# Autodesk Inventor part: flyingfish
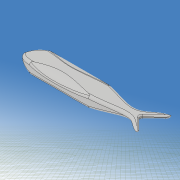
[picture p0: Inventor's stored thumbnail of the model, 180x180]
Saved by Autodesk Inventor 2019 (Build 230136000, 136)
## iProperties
Created: 2020-12
Part Number: flyingfish
Material: 一般
Document SubType Name: Modeling
Designer: kikut
Density: 1 g/cm^3
Appearance: 既定
Mass: 87.6477 g
Surface Area: 156.124 cm^2
Volume: 87.6477 cm^3
Author: kikut
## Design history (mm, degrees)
sketch "スケッチ1"
  geometry: L1 (-100, -20)-(100, -20); L2 (100, -20)-(100, 20); L3 (100, 20)-(-100, 20); L4 (-100, 20)-(-100, -20); L5 (-100, -20)-(100, 20); L6 (100, -20)-(-100, 20); 1 further point
  constraints: 12 end point, 2 midpoint, 2 parallel, 1 horizontal, 1 perpendicular
  dimensions: "d0" = 40 distance of L3.end L1.start; "d1" = 200 distance of L2.end L3.end
extrude "押し出し1" new body sketch "スケッチ1" stored distance "d2" = 60; taper "d3" = 0 deg
sketch "スケッチ2"
  geometry: L1 (0, -60)-(0, 0) reference; L2 (200, -60)-(200, 0) reference; L3 (0, 0)-(200, 0) reference; L4 (200, -60)-(0, -60) reference; L5 (0, -26)-(0, -32); L6 (194, -10)-(194, -13); L7 (194, -13)-(174, -33); L8 (174, -33)-(200, -58); L9 (-20, 20)-(220, 20); L10 (220, 20)-(220, -100); L11 (220, -100)-(-20, -100); L12 (-20, -100)-(-20, 20); 12 further points
  constraints: 16 end point, 4 point on line, 2 parallel, 2 vertical, 1 horizontal, 1 perpendicular, 14 other
  dimensions: "d4" = 32 distance from line of point (32, -12) L1; "d5" = 50 horizontal distance of point (32, -12) point (82, -11); "d6" = 50 horizontal distance of point (132, -17) point (82, -11); "d7" = 12 distance from line of point (32, -12) L3; "d8" = 11 distance from line of point (82, -11) L3; "d10" = 17 distance from line of point (132, -17) L3; "d11" = 26 distance from line of L5.start L3; "d12" = 0 distance from line of point (200, -60) L4; "d13" = 28 distance from line of L5.end L4; "d14" = 12 distance from line of point (28, -48) L4; "d15" = 10 distance from line of point (80, -50) L4; "d16" = 16 distance from line of point (130, -44) L4; "d17" = 28 distance from line of point (28, -48) L1; "d19" = 50 horizontal distance of point (130, -44) point (80, -50); "d20" = 80 distance from line of point (80, -50) L1; "d21" = 6 distance from line of L6.start L2; "d22" = 36 distance from line of point (164, -24) L2; "d23" = 24 distance from line of point (176, -20) L2; "d24" = 10 distance from line of L6.start L3; "d25" = 20 distance from line of point (176, -20) L3; "d26" = 24 distance from line of point (164, -24) L3; "d27" = 40 distance from line of point (160, -40) L2; "d28" = 25 distance from line of point (175, -47.5) L2; "d29" = 12.5 distance from line of point (175, -47.5) L4; "d30" = 20 distance from line of L4 point (160, -40); "d31" = 3 distance of L6.start L6.end; "d32" = 33 distance from line of L7.end L3; "d33" = 26 distance from line of L7.end L2; "d34" = 2 distance of L8.end L2.start; "d35" = 120 distance of L11.end L9.start; "d36" = 240 distance of L10.end L11.end; "d37" = 20 distance between parallel lines of L1 L12; "d38" = 20 distance between parallel lines of L3 L9
extrude "押し出し2" cut sketch "スケッチ2" extent not by distance; stored distance "d39" = 0.02; taper "d40" = 0 deg
sketch "スケッチ8"
  geometry: L1 (-100, -20)-(-100, 20) reference; L2 (100, 20)-(100, -20) reference; L3 (-142.805, 0)-(142.831, 0) reference; L4 (110, 30)-(-110, 30); L5 (-110, 30)-(-110, -30); L6 (-110, -30)-(110, -30); L7 (110, -30)-(110, 30); L8 (110, 30)-(-110, -30); L9 (-110, 30)-(110, -30); L10 (-100, -2)-(-100, 2); L11 (100, -3)-(100, 3); 7 further points
  constraints: 16 end point, 4 point on line, 2 midpoint, 2 parallel, 2 perpendicular, 1 collinear, 1 horizontal, 10 other
  dimensions: "d93" = 2 vertical distance of point (0, 0) L10.end; "d94" = 2 vertical distance of L10.start point (0, 0); "d95" = 35 distance from line of point (-65, -10) L1; "d96" = 0 horizontal distance of point (-65, 10) point (-65, -10); "d97" = 10 vertical distance of point (0, 0) point (-65, -10); "d98" = 10 vertical distance of point (-65, 10) point (0, 0); "d99" = 100 distance from line of point (0, -10) L1; "d100" = 0 horizontal distance of point (0, 10) point (0, -10); "d101" = 10 distance of point (0, -10) point (0, 0); "d102" = 10 distance of point (0, 0) point (0, 10); "d103" = 160 distance from line of point (60, -4) L1; "d104" = 0 horizontal distance of point (60, 4) point (60, -4); "d105" = 4 distance from line of L3 point (60, -4); "d106" = 4 distance from line of L3 point (60, 4); "d107" = 3 distance from line of L11.start L3; "d108" = 3 distance from line of L11.end L3; "d109" = 220 distance of L5.end L6.end; "d110" = 60 distance of L4.end L5.end
extrude "押し出し6" cut sketch "スケッチ8" extent not by distance; stored distance "d111" = 10; taper "d112" = 0 deg
sketch "スケッチ9" dims "d113" = 20, "d114" = 12
  geometry: L1 (-29, -18)-(21, -18); L2 (21, -18)-(21, 22); L3 (21, 22)-(-29, 22); L4 (-29, 22)-(-29, -18); L5 (-29, -18)-(21, 22); L6 (21, -18)-(-29, 22); 2 further points; 1 other entity
  constraints: 12 end point, 2 midpoint, 2 parallel, 1 coincident, 1 horizontal, 1 perpendicular, 2 other
  dimensions: "d115" = 50 distance of L2.end L3.end; "d116" = 40 distance of L1.end L2.end
extrude "押し出し7" cut sketch "スケッチ9" distance "d117" = 150; taper "d118" = 0 deg
fillet "フィレット4" dims "d119" = 4
fillet "フィレット5" dims "d120" = 4
fillet "フィレット6" dims "d121" = 2
node "ソリッド1"
